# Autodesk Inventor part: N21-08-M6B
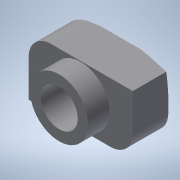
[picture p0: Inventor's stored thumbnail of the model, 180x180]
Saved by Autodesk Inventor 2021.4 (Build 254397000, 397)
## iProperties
Created: 2019-02
Part Number: N21-08-M6B
Material: Generico
Document SubType Name: Modeling
Designer: daniele.berto
Mass: 0.546178 g
Surface Area: 5.88072 cm^2
Volume: 0.546178 cm^3
Density: 1 g/cm^3
Appearance: Default
Title: 5037.step
DCM_MASS: 0.0
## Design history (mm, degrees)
feature "M6 ÂÝÎÆ¿×1"
node "Solido1"
